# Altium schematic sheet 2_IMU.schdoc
size 307 x 218 mm; Symbol: Sheet-Symbol_A4; Device: Sheet-Symbol_A4; @Project Name: Hexapod; @Page Count: 5; @Update Date: 2024-12-14; @Create Date: 2024-10-16; @Schematic Name: Schematic1; @Page No: 2; @Page Name: IMU; Company: EasyEDA.com; Version: V1.0; Page Size: A4; @Create Time: 14:36:57; @Update Time: 01:49:26; Title Block Position: 3; Width: 1170; Height: 825; Region Start: 1; X Region Count: 6; Y Region Count: 4; Blade Width: 10; @Board Name: Hexapod
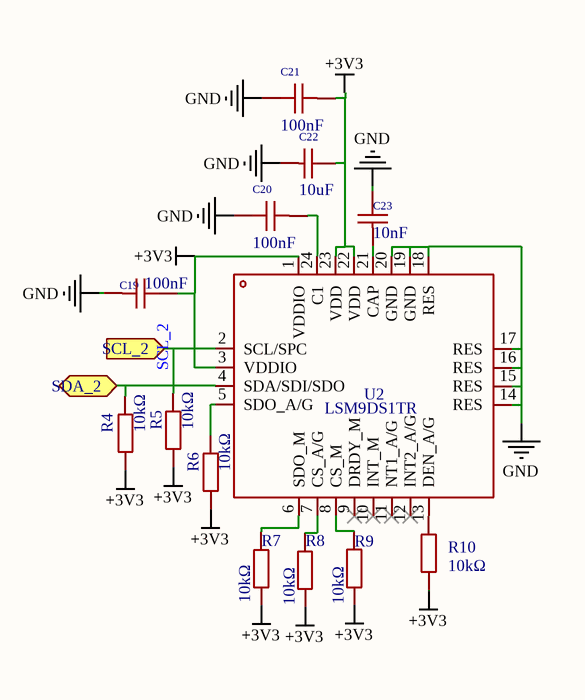
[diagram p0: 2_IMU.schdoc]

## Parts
C19  100nF  [C0402]
C20  100nF  [C0402]
C21  100nF  [C0402]
C22  10uF  [C0402]
C23  10nF  [C0402]
R4  10kΩ  [R0402]
R5  10kΩ  [R0402]
R6  10kΩ  [R0402]
R7  10kΩ  [R0402]
R8  10kΩ  [R0402]
R9  10kΩ  [R0402]
R10  10kΩ  [R0402]
U2  LSM9DS1TR  [LGA-24_L3.5-W3.0-P0.43-TL]

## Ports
SCL_2 (in), SDA_2 (bidir)

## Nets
+3V3: C19.1 C21.2 C22.2 R4.2 R5.2 R6.2 R7.2 R8.1 R9.1 R10.2 U2.1(VDDIO) U2.3(VDDIO) U2.22(VDD) U2.23(VDD)
GND: C19.2 C20.1 C21.1 C22.1 C23.2 U2.14(RES) U2.15(RES) U2.16(RES) U2.17(RES) U2.18(RES) U2.19(GND) U2.20(GND)
SCL_2: R5.1 U2.2(SCL/SPC) ; port SCL_2
SDA_2: R4.1 U2.4(SDA/SDI/SDO) ; port SDA_2
NetC20_2: C20.2 U2.24(C1)
NetC23_1: C23.1 U2.21(CAP)
NetR6_1: R6.1 U2.5(SDO_A/G)
NetR7_1: R7.1 U2.6(SDO_M)
NetR8_2: R8.2 U2.7(CS_A/G)
NetR9_2: R9.2 U2.8(CS_M)
NetR10_1: R10.1 U2.13(DEN_A/G)

Not connected (* = marked no-connect by the designer): U2 9(DRDY_M)* 10(INT_M)* 11(NT1_A/G)* 12(INT2_A/G)*

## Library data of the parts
C19-C21 = CC0402KRX7R7BB104: Manufacturer: YAGEO(国巨); Add into BOM: yes; Tolerance: ±10%
C22 = CL05A106MQ5NUNC: Manufacturer: SAMSUNG(三星); Add into BOM: yes; Tolerance: ±20%
C23 = CC0402KRX7R9BB103: Manufacturer: YAGEO(国巨); Add into BOM: yes; Tolerance: ±10%
R4-R10 = RC0402FR-0710KL: Manufacturer: YAGEO(国巨); Add into BOM: yes; Tolerance: ±1%; Temperature Coefficient: ±100ppm/℃
U2 = LSM9DS1TR: Manufacturer: ST(意法半导体); Add into BOM: yes; Sensor Type: 加速度计陀螺仪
